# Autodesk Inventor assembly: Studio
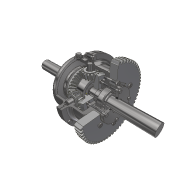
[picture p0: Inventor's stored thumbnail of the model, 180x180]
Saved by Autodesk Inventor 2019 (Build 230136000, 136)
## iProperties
Created: 2019-01
Part Number: Studio
Document SubType Name: Assembly
Designer: m.vorobev
Author: m.vorobev
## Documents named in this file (31)
- C:\Users\m.vorobev.TRINITY\Documents\Inventor\00-000.06.21.21.00\Studio.iam
- C:\Users\m.vorobev.TRINITY\Documents\Inventor\00-000.06.21.21.00\00-000.06.21.21.10.ipt
- C:\Users\m.vorobev.TRINITY\Documents\Inventor\00-000.06.21.21.00\00-000.06.21.21.01.ipt
- C:\Users\m.vorobev.TRINITY\Documents\Inventor\00-000.06.21.21.00\00-000.06.21.21.02.ipt
- C:\Users\m.vorobev.TRINITY\Documents\Inventor\00-000.06.21.21.00\Content Center Files\en-US\Bolt GOST 7798-78\Bolt  M10-6g×35(S16) GOST 7798-70.ipt
- C:\Users\m.vorobev.TRINITY\Documents\Inventor\00-000.06.21.21.00\Content Center Files\en-US\GOST 6402-70\Washer  10 L GOST 6402-70.ipt
- C:\Users\m.vorobev.TRINITY\Documents\Inventor\00-000.06.21.21.00\Content Center Files\en-US\GOST 5916-70\Nut M10-6H GOST 5916-70.ipt
- C:\Users\m.vorobev.TRINITY\Documents\Inventor\00-000.06.21.21.00\00-000.06.21.21.15.ipt
- C:\Users\m.vorobev.TRINITY\Documents\Inventor\00-000.06.21.21.00\00-000.06.21.21.05.ipt
- C:\Users\m.vorobev.TRINITY\Documents\Inventor\00-000.06.21.21.00\Key 2-36x20x100 GOST 23360-78.ipt
- C:\Users\m.vorobev.TRINITY\Documents\Inventor\00-000.06.21.21.00\Content Center Files\en-US\Stud GOST 22034-76\Stud M10-6g×45 GOST 22034-76.ipt
- C:\Users\m.vorobev.TRINITY\Documents\Inventor\00-000.06.21.21.00\00-000.06.21.21.07.ipt
- C:\Users\m.vorobev.TRINITY\Documents\Inventor\00-000.06.21.21.00\00-000.06.21.21.11,12,13\00-000.06.21.21.12.ipt
- C:\Users\m.vorobev.TRINITY\Documents\Inventor\00-000.06.21.21.00\00-000.06.21.21.11,12,13.ipt
- C:\Users\m.vorobev.TRINITY\Documents\Inventor\00-000.06.21.21.00\00-000.06.21.21.03.ipt
- C:\Users\m.vorobev.TRINITY\Documents\Inventor\00-000.06.21.21.00\00-000.06.21.21.04.ipt
- C:\Users\m.vorobev.TRINITY\Documents\Inventor\00-000.06.21.21.00\Key 2-12x8x28 GOST 23360-78.ipt
- C:\Users\m.vorobev.TRINITY\Documents\Inventor\00-000.06.21.21.00\Content Center Files\en-US\Nut GOST 12460-67\Nut 7003-0141 GOST 12460-67.ipt
- C:\Users\m.vorobev.TRINITY\Documents\Inventor\00-000.06.21.21.00\00-000.06.21.21.11,12,13\00-000.06.21.21.11.ipt
- C:\Users\m.vorobev.TRINITY\Documents\Inventor\00-000.06.21.21.00\Content Center Files\en-US\GOST 8338-75\Bearing 309 GOST 8338-75.ipt
- C:\Users\m.vorobev.TRINITY\Documents\Inventor\00-000.06.21.21.00\00-000.06.21.21.11,12,13\00-000.06.21.21.13.ipt
- C:\Users\m.vorobev.TRINITY\Documents\Inventor\00-000.06.21.21.00\00-000.06.21.21.08,09\00-000.06.21.21.08.ipt
- C:\Users\m.vorobev.TRINITY\Documents\Inventor\00-000.06.21.21.00\00-000.06.21.21.08,09.ipt
- C:\Users\m.vorobev.TRINITY\Documents\Inventor\00-000.06.21.21.00\00-000.06.21.21.08,09\00-000.06.21.21.09.ipt
- C:\Users\m.vorobev.TRINITY\Documents\Inventor\00-000.06.21.21.00\00-000.06.21.21.29.ipt
- C:\Users\m.vorobev.TRINITY\Documents\Inventor\00-000.06.21.21.00\Content Center Files\en-US\GOST 6402-70\Washer  8 L GOST 6402-70.ipt
- C:\Users\m.vorobev.TRINITY\Documents\Inventor\00-000.06.21.21.00\Content Center Files\en-US\Bolt GOST 7798-78\Bolt  M8-6g×35(S13) GOST 7798-70.ipt
- C:\Users\m.vorobev.TRINITY\Documents\Inventor\00-000.06.21.21.00\00-000.06.21.21.06.ipt
- C:\Users\m.vorobev.TRINITY\Documents\Inventor\00-000.06.21.21.00\00-000.06.21.21.17.ipt
- C:\Users\m.vorobev.TRINITY\Documents\Inventor\00-000.06.21.21.00\00-000.06.21.21.16.ipt
- C:\Users\m.vorobev.TRINITY\Documents\Inventor\00-000.06.21.21.00\00-000.06.21.21.14.ipt
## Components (104 placed, 28 different names)
1. 00-000.06.21.21.10:1 — Mate:4, Mate:5, Mate:6, Mate:7, Mate:8, Mate:16, Mate:23
2. 00-000.06.21.21.01:1 — Mate:19, Insert:70, Mate:21, Insert:90, Mate:22, Insert:93, Mate:24, Insert:95
3. 00-000.06.21.21.02:1 — Insert:19, Mate:1, Mate:2, Mate:3, Insert:20, Insert:21, Mate:18, Insert:53, Insert:71, Mate:20, Mate:23, Insert:95
4. 00-000.06.21.21.15:1 — Insert:19
5. 00-000.06.21.21.05:1 — Angle:1, Insert:21
6. Key 2-36x20x100 GOST 23360-78:1 — Mate:1, Mate:2, Mate:3, Angle:1
7. 00-000.06.21.21.07:1 — Mate:14, Insert:44, Mate:15, Mate:17, Insert:45, Insert:46, Insert:47, Insert:48, Mate:24, Drive
8. 00-000.06.21.21.12:1 — Insert:38, Insert:44
9. 00-000.06.21.21.12:2 — Insert:39, Insert:47
10. 00-000.06.21.21.12:3 — Insert:41, Insert:46
11. 00-000.06.21.21.12:4 — Insert:40, Insert:45
12. 00-000.06.21.21.03:1 — Insert:38
13. 00-000.06.21.21.03:2 — Insert:39
14. 00-000.06.21.21.03:3 — Insert:40
15. 00-000.06.21.21.03:4 — Insert:41
16. 00-000.06.21.21.04:1 — Mate:7, Mate:8, Insert:42, Mate:15, Insert:49
17. Key 2-12x8x28 GOST 23360-78:1 — Mate:4, Mate:5, Mate:6
18. 00-000.06.21.21.10:2 — Mate:16, Mate:22
19. 00-000.06.21.21.04:2 — Mate:17, Insert:50
20. Key 2-12x8x28 GOST 23360-78:2
21. 00-000.06.21.21.11:5 — Insert:48
22. 00-000.06.21.21.13:6 — Insert:49
23. 00-000.06.21.21.13:7 — Insert:50
24. 00-000.06.21.21.08:1 — Insert:51, Mate:18, Insert:53, Insert:80
25. 00-000.06.21.21.09:2 — Insert:52, Insert:63, Insert:67, Insert:68, Insert:69, Mate:19, Insert:70, Insert:89, Insert:91
26. 00-000.06.21.21.29:1 — Insert:51
27. 00-000.06.21.21.29:2 — Insert:52
28. 00-000.06.21.21.06:1 — Insert:71, Mate:20, Insert:76, Insert:77, Insert:78, Insert:79
29. 00-000.06.21.21.06:2 — Mate:21, Insert:90
30. 00-000.06.21.21.17:1 — Insert:93, Insert:94
31. 00-000.06.21.21.16:1 — Insert:91
32. 00-000.06.21.21.14:1 — Insert:94
33. Bolt GOST 7798-70 M10-6g×35(S16):1
34. Bolt GOST 7798-70 M10-6g×35(S16):2
35. Bolt GOST 7798-70 M10-6g×35(S16):3
36. Bolt GOST 7798-70 M10-6g×35(S16):4
37. Bolt GOST 7798-70 M10-6g×35(S16):5
38. Bolt GOST 7798-70 M10-6g×35(S16):6
39. Washer GOST 6402-70 10 L:1
40. Washer GOST 6402-70 10 L:2
41. Washer GOST 6402-70 10 L:3
42. Washer GOST 6402-70 10 L:4
43. Washer GOST 6402-70 10 L:5
44. Washer GOST 6402-70 10 L:6
45. Nut GOST 5916-70 M10:1
46. Nut GOST 5916-70 M10:2
47. Nut GOST 5916-70 M10:3
48. Nut GOST 5916-70 M10:4
49. Nut GOST 5916-70 M10:5
50. Nut GOST 5916-70 M10:6
51. Washer GOST 6402-70 10 L:7 — Insert:28
52. Washer GOST 6402-70 10 L:8 — Insert:33
53. Washer GOST 6402-70 10 L:9 — Insert:32
54. Washer GOST 6402-70 10 L:10 — Insert:31
55. Washer GOST 6402-70 10 L:11 — Insert:30
56. Washer GOST 6402-70 10 L:12 — Insert:29
57. Nut GOST 5916-70 M10:7 — Insert:28
58. Nut GOST 5916-70 M10:8 — Insert:33
59. Nut GOST 5916-70 M10:9 — Insert:29
60. Nut GOST 5916-70 M10:10 — Insert:30
61. Nut GOST 5916-70 M10:11 — Insert:31
62. Nut GOST 5916-70 M10:12 — Insert:32
63. Nut GOST 12460-67 7003-0141:1 — Insert:42, Mate:14
64. Nut GOST 12460-67 7003-0141:3
65. Bearing GOST 8338-75 309:1 — Insert:89
66. Washer GOST 6402-70 8 L:1
67. Washer GOST 6402-70 8 L:2 — Insert:59
68. Washer GOST 6402-70 8 L:3 — Insert:61
69. Washer GOST 6402-70 8 L:4 — Insert:60
70. Bolt GOST 7798-70 M8-6g×35(S13):1
71. Bolt GOST 7798-70 M8-6g×35(S13):2 — Insert:59
72. Bolt GOST 7798-70 M8-6g×35(S13):3 — Insert:61
73. Bolt GOST 7798-70 M8-6g×35(S13):4 — Insert:60
74. Washer GOST 6402-70 8 L:5 — Insert:63
75. Bolt GOST 7798-70 M8-6g×35(S13):5
76. Washer GOST 6402-70 8 L:6 — Insert:68
77. Bolt GOST 7798-70 M8-6g×35(S13):6
78. Washer GOST 6402-70 8 L:7 — Insert:69
79. Bolt GOST 7798-70 M8-6g×35(S13):7
80. Washer GOST 6402-70 8 L:8 — Insert:67
81. Bolt GOST 7798-70 M8-6g×35(S13):8
82. Washer GOST 6402-70 8 L:9 — Insert:78
83. Bolt GOST 7798-70 M8-6g×35(S13):9
84. Washer GOST 6402-70 8 L:10 — Insert:76
85. Bolt GOST 7798-70 M8-6g×35(S13):10
86. Washer GOST 6402-70 8 L:11 — Insert:79
87. Bolt GOST 7798-70 M8-6g×35(S13):11
88. Washer GOST 6402-70 8 L:12 — Insert:77
89. Bolt GOST 7798-70 M8-6g×35(S13):12
90. Bearing GOST 8338-75 309:2 — Insert:80
91. Washer GOST 6402-70 8 L:13
92. Bolt GOST 7798-70 M8-6g×35(S13):13
93. Washer GOST 6402-70 8 L:14
94. Bolt GOST 7798-70 M8-6g×35(S13):14
95. Washer GOST 6402-70 8 L:15
96. Bolt GOST 7798-70 M8-6g×35(S13):15
97. Washer GOST 6402-70 8 L:16
98. Bolt GOST 7798-70 M8-6g×35(S13):16
99. Stud GOST 22034-76 M10-6g×45:1 — Insert:20
100. Stud GOST 22034-76 M10-6g×45:2
101. Stud GOST 22034-76 M10-6g×45:3
102. Stud GOST 22034-76 M10-6g×45:4
103. Stud GOST 22034-76 M10-6g×45:5
104. Stud GOST 22034-76 M10-6g×45:6
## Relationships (65: Insert 44, Mate 19, Angle 2)
- Insert:19: 00-000.06.21.21.02:1 ↔ 00-000.06.21.21.15:1
- Mate:1: 00-000.06.21.21.02:1 ↔ Key 2-36x20x100 GOST 23360-78:1
- Mate:2: 00-000.06.21.21.02:1 ↔ Key 2-36x20x100 GOST 23360-78:1
- Mate:3: 00-000.06.21.21.02:1 ↔ Key 2-36x20x100 GOST 23360-78:1
- Insert:20: 00-000.06.21.21.02:1 ↔ Stud GOST 22034-76 M10-6g×45:1
- Angle:1: 00-000.06.21.21.05:1 ↔ Key 2-36x20x100 GOST 23360-78:1
- Insert:21: 00-000.06.21.21.02:1 ↔ 00-000.06.21.21.05:1
- Insert:28: Washer GOST 6402-70 10 L:7 ↔ Nut GOST 5916-70 M10:7
- Insert:29: Washer GOST 6402-70 10 L:12 ↔ Nut GOST 5916-70 M10:9
- Insert:30: Washer GOST 6402-70 10 L:11 ↔ Nut GOST 5916-70 M10:10
- Insert:31: Washer GOST 6402-70 10 L:10 ↔ Nut GOST 5916-70 M10:11
- Insert:32: Washer GOST 6402-70 10 L:9 ↔ Nut GOST 5916-70 M10:12
- Insert:33: Washer GOST 6402-70 10 L:8 ↔ Nut GOST 5916-70 M10:8
- Insert:38: 00-000.06.21.21.12:1 ↔ 00-000.06.21.21.03:1
- Insert:39: 00-000.06.21.21.12:2 ↔ 00-000.06.21.21.03:2
- Insert:40: 00-000.06.21.21.12:4 ↔ 00-000.06.21.21.03:3
- Insert:41: 00-000.06.21.21.12:3 ↔ 00-000.06.21.21.03:4
- Mate:4: 00-000.06.21.21.10:1 ↔ Key 2-12x8x28 GOST 23360-78:1
- Mate:5: 00-000.06.21.21.10:1 ↔ Key 2-12x8x28 GOST 23360-78:1
- Mate:6: 00-000.06.21.21.10:1 ↔ Key 2-12x8x28 GOST 23360-78:1
- Mate:7: 00-000.06.21.21.10:1 ↔ 00-000.06.21.21.04:1
- Mate:8: 00-000.06.21.21.10:1 ↔ 00-000.06.21.21.04:1
- Insert:42: 00-000.06.21.21.04:1 ↔ Nut GOST 12460-67 7003-0141:1
- Mate:14: 00-000.06.21.21.07:1 ↔ Nut GOST 12460-67 7003-0141:1
- Insert:44: 00-000.06.21.21.07:1 ↔ 00-000.06.21.21.12:1
- Mate:15: 00-000.06.21.21.07:1 ↔ 00-000.06.21.21.04:1
- Mate:16: 00-000.06.21.21.10:1 ↔ 00-000.06.21.21.10:2
- Mate:17: 00-000.06.21.21.07:1 ↔ 00-000.06.21.21.04:2
- Insert:45: 00-000.06.21.21.07:1 ↔ 00-000.06.21.21.12:4
- Insert:46: 00-000.06.21.21.07:1 ↔ 00-000.06.21.21.12:3
- Insert:47: 00-000.06.21.21.07:1 ↔ 00-000.06.21.21.12:2
- Insert:48: 00-000.06.21.21.07:1 ↔ 00-000.06.21.21.11:5
- Insert:49: 00-000.06.21.21.04:1 ↔ 00-000.06.21.21.13:6
- Insert:50: 00-000.06.21.21.04:2 ↔ 00-000.06.21.21.13:7
- Insert:51: 00-000.06.21.21.08:1 ↔ 00-000.06.21.21.29:1
- Insert:52: 00-000.06.21.21.09:2 ↔ 00-000.06.21.21.29:2
- Mate:18: 00-000.06.21.21.02:1 ↔ 00-000.06.21.21.08:1
- Insert:53: 00-000.06.21.21.02:1 ↔ 00-000.06.21.21.08:1
- Insert:59: Washer GOST 6402-70 8 L:2 ↔ Bolt GOST 7798-70 M8-6g×35(S13):2
- Insert:60: Washer GOST 6402-70 8 L:4 ↔ Bolt GOST 7798-70 M8-6g×35(S13):4
- Insert:61: Washer GOST 6402-70 8 L:3 ↔ Bolt GOST 7798-70 M8-6g×35(S13):3
- Insert:63: 00-000.06.21.21.09:2 ↔ Washer GOST 6402-70 8 L:5
- Insert:67: 00-000.06.21.21.09:2 ↔ Washer GOST 6402-70 8 L:8
- Insert:68: 00-000.06.21.21.09:2 ↔ Washer GOST 6402-70 8 L:6
- Insert:69: 00-000.06.21.21.09:2 ↔ Washer GOST 6402-70 8 L:7
- Mate:19: 00-000.06.21.21.01:1 ↔ 00-000.06.21.21.09:2
- Insert:70: 00-000.06.21.21.01:1 ↔ 00-000.06.21.21.09:2
- Insert:71: 00-000.06.21.21.02:1 ↔ 00-000.06.21.21.06:1
- Mate:20: 00-000.06.21.21.02:1 ↔ 00-000.06.21.21.06:1
- Insert:76: 00-000.06.21.21.06:1 ↔ Washer GOST 6402-70 8 L:10
- Insert:77: 00-000.06.21.21.06:1 ↔ Washer GOST 6402-70 8 L:12
- Insert:78: 00-000.06.21.21.06:1 ↔ Washer GOST 6402-70 8 L:9
- Insert:79: 00-000.06.21.21.06:1 ↔ Washer GOST 6402-70 8 L:11
- Insert:80: 00-000.06.21.21.08:1 ↔ Bearing GOST 8338-75 309:2
- Mate:21: 00-000.06.21.21.01:1 ↔ 00-000.06.21.21.06:2
- Insert:89: 00-000.06.21.21.09:2 ↔ Bearing GOST 8338-75 309:1
- Insert:90: 00-000.06.21.21.01:1 ↔ 00-000.06.21.21.06:2
- Mate:22: 00-000.06.21.21.01:1 ↔ 00-000.06.21.21.10:2
- Mate:23: 00-000.06.21.21.10:1 ↔ 00-000.06.21.21.02:1
- Insert:91: 00-000.06.21.21.09:2 ↔ 00-000.06.21.21.16:1
- Insert:93: 00-000.06.21.21.01:1 ↔ 00-000.06.21.21.17:1
- Insert:94: 00-000.06.21.21.17:1 ↔ 00-000.06.21.21.14:1
- Mate:24: 00-000.06.21.21.01:1 ↔ 00-000.06.21.21.07:1
- Insert:95: 00-000.06.21.21.01:1 ↔ 00-000.06.21.21.02:1
- Drive [Angle]: 00-000.06.21.21.07:1
## Named parameters: d52_d49 = 0, d53_d50 = 0, d54_d51 = 0, d55_d45 = 0, d56_d46 = 0, d57_d47 = 0, d58_d48 = 0, d88_d84 = 0, d90_d88_d84 = 0, d91_d88_d84 = 0, d92_d88_d84 = 0, d100_d84 = 0, d101_d100_d84 = 0, d102_d100_d84 = 0, d103_d100_d84 = 0, d109_d100_d84 = 0, d110_d101_d100_d84 = 0, d111_d102_d100_d84 = 0, d112_d103_d100_d84 = 0, d113_d104 = 0, d114_d105 = 0, d115_d106 = 0, d116_d107 = 0
